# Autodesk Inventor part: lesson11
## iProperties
Author: Administrator
Created: 2000-12
Part Number: lesson11
Document SubType Name: Modeling
Designer: Administrator
Control State: 0
Master: False
Checked Out: False
PropertySet Name: Design Tracking Control
Shininess: 0.0
PropertySet Name: _Private Model Information
Density: 0.0
Volumn: 0.0
Area: 0.0
PropertySet Name: Model Information
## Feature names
1. Extrusion1
2. Extrusion2
3. Hole1
4. Extrusion3
